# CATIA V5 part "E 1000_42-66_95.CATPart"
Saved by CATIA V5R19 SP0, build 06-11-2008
Definition: E 1000_42-66_95
Nomenclature: E 1000_42-66_95
Description: PART--DESC
Material "Steel": density 7860 kg/m3, Young's modulus 2e+11 Pa, Poisson ratio 0.266, thermal expansion 1.17e-05 1/K
Bounding box of the stored display mesh (mm): x 249.7 to 308.3, y 199.71 to 258.29, z -161 to 12
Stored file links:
  G:\UTB\Kombinované\Bakalářská práce\Catia\FORMA\E 1000_42-66_95.CATPart
  D:\Aplikace\CATIA\Nová složka\win_b64\startup\materials\Catalog.CATMaterial
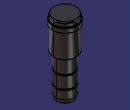
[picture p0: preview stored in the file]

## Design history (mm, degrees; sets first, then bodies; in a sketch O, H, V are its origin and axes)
Body1 "E 1000_42-66_95" (main body)
  Solid1: solid without history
